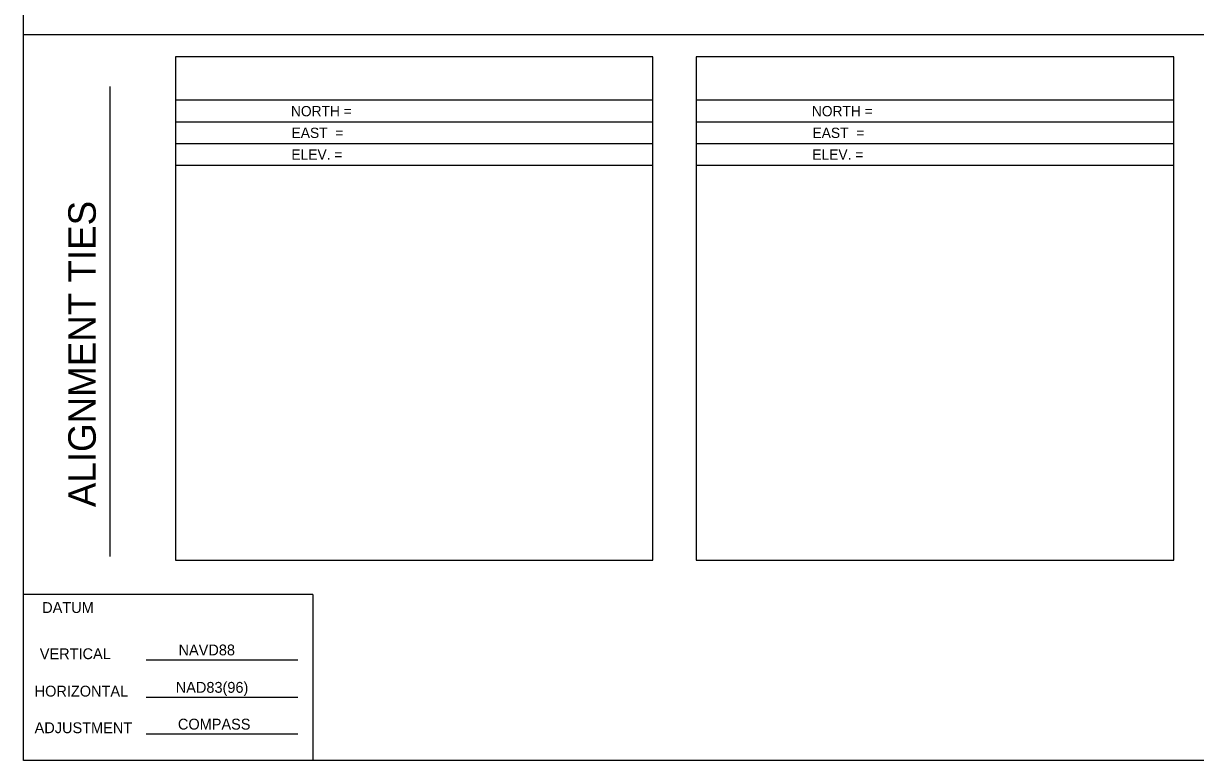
# Model space of a CAD drawing. Extents: x 1603676 to 1604316, y 320315 to 320735.
# Drawn here: x 1603675.9 to 1603945.9, y 320314.6 to 320484.5 of the extents above; entities that cross this region are included whole.
import ezdxf

# ---------------------------------------------------------------- set-up
doc = ezdxf.new("R2010")
doc.units = 0
doc.layers.add('NBL1', color=7, linetype='Continuous')
doc.layers.add('NBL2', color=7, linetype='Continuous')

msp = doc.modelspace()

# ---------------------------------------------------------------- linework, layer by layer
at = {"layer": 'NBL1'}
for p, q in [((1603675.93, 320481.9), (1604315.93, 320481.9)), ((1603695.93, 320361.57), (1603695.93, 320469.9)), ((1603820.92, 320466.73), (1603710.92, 320466.73)), ((1603940.92, 320466.73), (1603830.92, 320466.73)), ((1603820.92, 320461.73), (1603710.92, 320461.73)), ((1603940.92, 320461.73), (1603830.92, 320461.73)), ((1603820.92, 320456.73), (1603710.92, 320456.73)), ((1603940.92, 320456.73), (1603830.92, 320456.73)), ((1603820.92, 320451.73), (1603710.92, 320451.73)), ((1603940.92, 320451.73), (1603830.92, 320451.73))]:
    msp.add_line(p, q, dxfattribs=at)
for points in [[(1604315.93, 320314.57), (1603675.93, 320314.57), (1603675.93, 320734.57), (1604315.93, 320734.57)], [(1603710.92, 320360.73), (1603820.92, 320360.73), (1603820.92, 320476.73), (1603710.92, 320476.73)], [(1603830.92, 320360.73), (1603940.92, 320360.73), (1603940.92, 320476.73), (1603830.92, 320476.73)]]:
    msp.add_lwpolyline(points, close=True, dxfattribs=at)
at = {"layer": 'NBL2'}
for p, q in [((1603742.59, 320352.82), (1603675.93, 320352.82)), ((1603742.59, 320352.82), (1603742.59, 320314.57)), ((1603742.59, 320352.82), (1603742.59, 320314.57)), ((1603704.17, 320337.76), (1603739.17, 320337.76)), ((1603704.17, 320329.17), (1603739.17, 320329.17)), ((1603704.17, 320320.73), (1603739.17, 320320.73))]:
    msp.add_line(p, q, dxfattribs=at)

# ---------------------------------------------------------------- texts
at = {"layer": 'NBL1'}
for s, p in [('NORTH =             ', (1603737.54, 320463.05)), ('NORTH =             ', (1603857.54, 320463.05)), ('EAST  =             ', (1603737.69, 320458.05)), ('EAST  =             ', (1603857.69, 320458.05)), ('ELEV. =             ', (1603737.65, 320453.05)), ('ELEV. =             ', (1603857.65, 320453.05))]:
    msp.add_text(s, height=2.375, dxfattribs=at).set_placement(p)
msp.add_text('ALIGNMENT TIES', height=6.3332, rotation=90, dxfattribs=at).set_placement((1603692.59, 320372.97))
at = {"layer": 'NBL2'}
for s, p in [('DATUM', (1603680.24, 320348.58)), ('  NAVD88  ', (1603709.79, 320338.81)), ('HORIZONTAL', (1603678.5, 320329.32)), ('NAD83(96)  ', (1603711.01, 320330.19)), ('ADJUSTMENT', (1603678.5, 320320.88)), (' COMPASS  ', (1603710.58, 320321.71))]:
    msp.add_text(s, height=2.5, dxfattribs=at).set_placement(p)
msp.add_text('VERTICAL', height=2.5, rotation=0.1439, dxfattribs=at).set_placement((1603679.7, 320337.91))

doc.saveas('drawing.dxf')
